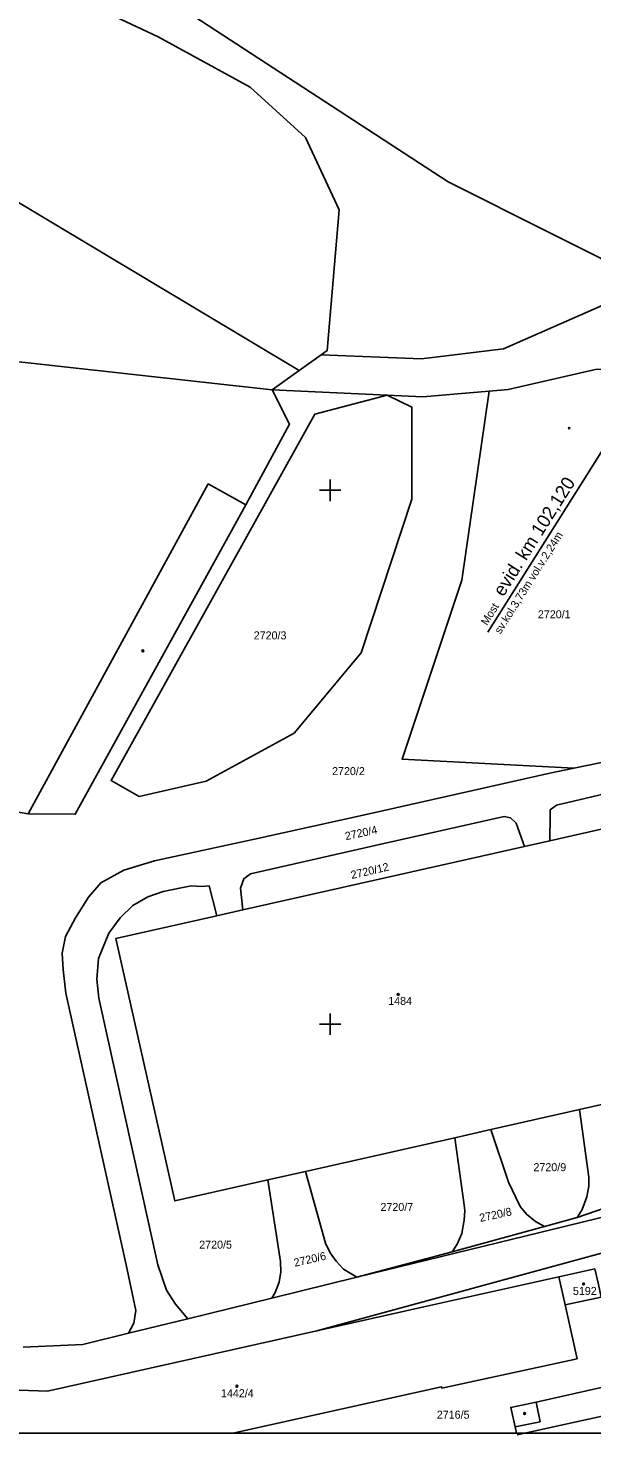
# Model space of a CAD drawing. Extents: x -800194 to -799078, y -1007177 to -1006597.
# Drawn here: x -799956.6 to -799850.9, y -1007177 to -1006913.4 of the extents above; entities that cross this region are included whole.
import ezdxf

# ---------------------------------------------------------------- set-up
doc = ezdxf.new("R2010")
doc.units = 0
for name, color, linetype in [('Legenda 1', 7, 'Continuous'), ('Ramove udaje', 7, 'Continuous'), ('Vrstva 18', 7, 'Continuous'), ('Vrstva 49', 7, 'Continuous'), ('Vrstva 53', 7, 'Continuous'), ('Vrstva 55', 7, 'Continuous'), ('Vrstva 56', 7, 'Continuous'), ('Vrstva 57', 7, 'Continuous'), ('Vrstva 59', 7, 'Continuous')]:
    doc.layers.add(name, color=color, linetype=linetype)

msp = doc.modelspace()

# ---------------------------------------------------------------- linework, layer by layer
at = {"layer": 'Legenda 1'}
msp.add_lwpolyline([(-800193.4, -1007176.65), (-799312.4, -1007176.65), (-799312.4, -1006766.65), (-800193.4, -1006766.65)], close=True, dxfattribs=at)
at = {"layer": 'Ramove udaje'}
for p, q in [((-799900, -1006998), (-799900, -1007002)), ((-799902, -1007000), (-799900, -1007000)), ((-799900, -1007000), (-799898, -1007000)), ((-799900, -1007098), (-799900, -1007102)), ((-799902, -1007100), (-799900, -1007100)), ((-799900, -1007100), (-799898, -1007100))]:
    msp.add_line(p, q, dxfattribs=at)
at = {"layer": 'Vrstva 18'}
msp.add_line((-799827.91, -1006959.09), (-799870.44, -1007026.56), dxfattribs=at)
at = {"layer": 'Vrstva 49'}
for p, q in [((-799855.35, -1006988.18), (-799855, -1006988.53)), ((-799855.35, -1006988.53), (-799855, -1006988.18))]:
    msp.add_line(p, q, dxfattribs=at)
at = {"layer": 'Vrstva 53'}
msp.add_lwpolyline([(-799673.33, -1007118.14), (-799714.71, -1007110.97), (-799718.21, -1007083.69), (-799729.93, -1007087.54), (-799766.47, -1007095.84), (-799767.73, -1007094.8), (-799769.22, -1007093.56), (-799785.06, -1007080.42), (-799809.11, -1007056.81), (-799818.59, -1007034.4), (-799822.79, -1007029.13), (-799826.14, -1007024.13), (-799830.75, -1006966.73), (-799839.73, -1006961.33), (-799877.87, -1006942.17), (-799936.47, -1006903.99), (-799954.76, -1006895.45), (-799964.79, -1006890.84)], dxfattribs=at)
at = {"layer": 'Vrstva 55'}
for p, q in [((-799905.8, -1006977.56), (-800048.34, -1006892.35)), ((-799905.8, -1006977.56), (-799901.69, -1006974.63)), ((-799901.69, -1006974.63), (-799882.85, -1006975.35)), ((-799910.85, -1006981.15), (-799905.8, -1006977.56)), ((-799870.16, -1006981.42), (-799878.32, -1006982.12)), ((-799866.6, -1006981.12), (-799870.16, -1006981.42)), ((-799858.8, -1007053.02), (-799854.29, -1007052.07)), ((-799854.29, -1007052.07), (-799846.07, -1007050.35)), ((-799863.56, -1007066.73), (-799916.37, -1007078.61)), ((-799858.84, -1007065.67), (-799863.56, -1007066.73)), ((-799916.37, -1007078.61), (-799921.23, -1007079.7)), ((-799853.26, -1007116.03), (-799846.34, -1007114.47)), ((-799869.87, -1007119.78), (-799853.26, -1007116.03)), ((-799876.63, -1007121.3), (-799869.87, -1007119.78)), ((-799904.64, -1007127.61), (-799876.63, -1007121.3)), ((-799911.69, -1007129.2), (-799904.64, -1007127.61)), ((-799853.69, -1007136.27), (-799838.05, -1007130.83)), ((-799859.81, -1007137.94), (-799853.69, -1007136.27)), ((-799877.13, -1007142.66), (-799859.81, -1007137.94)), ((-799902.49, -1007157.51), (-799844.11, -1007141.59)), ((-799895.02, -1007147.45), (-799877.13, -1007142.66)), ((-799850.35, -1007145.84), (-799857.1, -1007147.35)), ((-799895.02, -1007147.45), (-799910.9, -1007151.34)), ((-799855.94, -1007152.6), (-799857.1, -1007147.35)), ((-799910.9, -1007151.34), (-799926.68, -1007155.21)), ((-799926.68, -1007155.21), (-799937.79, -1007157.93))]:
    msp.add_line(p, q, dxfattribs=at)
for points in [[(-799901.69, -1006974.63), (-799900.54, -1006973.82), (-799898.31, -1006947.43), (-799904.63, -1006933.89), (-799915, -1006924.46), (-799932.22, -1006915.03), (-799953.17, -1006905.18), (-799968.93, -1006898.86), (-799993.08, -1006892.39), (-800012.71, -1006890.11), (-800033.89, -1006890), (-800048.34, -1006892.35)], [(-799839.73, -1006961.33), (-799877.87, -1006942.17), (-799936.47, -1006903.99), (-799954.76, -1006895.45), (-799964.79, -1006890.84)], [(-800126.38, -1006954.46), (-800114.82, -1006956.57), (-800087.75, -1006960.99), (-799990.59, -1006972.38), (-799910.85, -1006981.15)], [(-799882.85, -1006975.35), (-799867.48, -1006973.49), (-799839.73, -1006961.33)], [(-799831.14, -1007046.62), (-799837.54, -1006984.31), (-799843.2, -1006977.69), (-799849.98, -1006977.29), (-799866.6, -1006981.12)], [(-799910.85, -1006981.15), (-799907.6, -1006987.58), (-799915.79, -1007002.7), (-799947.77, -1007060.68), (-799956.59, -1007060.62), (-799959.22, -1007060.2), (-799959.32, -1007060.77), (-799959.99, -1007068.95), (-799959.15, -1007100.86), (-799958.55, -1007123.98)], [(-799889.28, -1006982.17), (-799884.71, -1006984.4), (-799884.66, -1007001.67), (-799894.18, -1007030.47), (-799906.77, -1007045.52), (-799923.26, -1007054.52), (-799935.81, -1007057.35), (-799941.05, -1007054.37), (-799902.88, -1006985.7), (-799889.28, -1006982.17)], [(-799882.61, -1006982.49), (-799889.28, -1006982.17), (-799910.85, -1006981.15)], [(-799870.16, -1006981.42), (-799875.33, -1007016.85), (-799886.5, -1007050.4), (-799854.29, -1007052.07)], [(-799878.32, -1006982.12), (-799881.11, -1006982.36), (-799882.61, -1006982.49)], [(-799937.79, -1007157.93), (-799936.82, -1007156.03), (-799936.45, -1007153.7), (-799938.22, -1007145.09), (-799949.52, -1007094.24), (-799950.07, -1007089.8), (-799950.22, -1007086.71), (-799949.61, -1007083.61), (-799947.74, -1007080.12), (-799945.31, -1007076.24), (-799942.96, -1007073.53), (-799938.68, -1007071.19), (-799932.9, -1007069.42), (-799914.16, -1007065.36), (-799892.71, -1007060.59), (-799858.8, -1007053.02)], [(-799858.84, -1007065.67), (-799858.76, -1007060.77), (-799858.72, -1007059.86), (-799857.59, -1007058.97), (-799845.38, -1007056.13), (-799841.77, -1007056.79), (-799839.5, -1007058.21), (-799837.43, -1007060.68), (-799836.99, -1007067.77), (-799836.14, -1007072.71), (-799834.61, -1007079.6), (-799832.83, -1007084.94), (-799830.58, -1007092.52), (-799828.9, -1007096.44), (-799827.32, -1007101.2), (-799825.89, -1007106.02), (-799824.52, -1007111.92), (-799824.25, -1007121.19), (-799824.17, -1007122.98), (-799825.87, -1007124.09), (-799830.82, -1007128.75)], [(-799916.37, -1007078.61), (-799916.82, -1007074.54), (-799916.17, -1007072.79), (-799914.91, -1007071.85), (-799890.76, -1007066.36), (-799867.37, -1007061.12), (-799866.17, -1007061.36), (-799865.15, -1007062.35), (-799863.56, -1007066.73)], [(-799846.34, -1007114.47), (-799834.79, -1007111.87), (-799845.89, -1007062.76), (-799858.84, -1007065.67)], [(-799926.68, -1007155.21), (-799928.97, -1007152.5), (-799930.66, -1007149.85), (-799932.29, -1007145.14), (-799943.36, -1007095.14), (-799943.76, -1007091.6), (-799943.45, -1007087.73), (-799941.48, -1007082.96), (-799939.34, -1007080.12), (-799936.97, -1007077.8), (-799934.15, -1007076.19), (-799931.27, -1007075.17), (-799926.04, -1007074.1), (-799924.08, -1007074.23), (-799922.66, -1007074.11), (-799921.23, -1007079.7)], [(-799921.23, -1007079.7), (-799940.15, -1007083.96), (-799929.14, -1007133.13), (-799911.69, -1007129.2)], [(-799853.69, -1007136.27), (-799852.72, -1007134.73), (-799851.85, -1007132.41), (-799851.49, -1007130.4), (-799851.51, -1007128.69), (-799851.8, -1007126.44), (-799853.26, -1007116.03)], [(-799859.81, -1007137.94), (-799861.51, -1007136.99), (-799863.16, -1007135.61), (-799864.37, -1007134.2), (-799866.53, -1007129.66), (-799869.87, -1007119.78)], [(-799877.13, -1007142.66), (-799876.18, -1007141.27), (-799875.3, -1007139.22), (-799874.85, -1007136.77), (-799874.75, -1007134.96), (-799875, -1007132.95), (-799875.06, -1007132.59), (-799876.63, -1007121.3)], [(-799814.24, -1007125.43), (-799822.76, -1007128.21), (-799844.82, -1007135.16), (-799895.02, -1007147.45)], [(-799895.02, -1007147.45), (-799897.49, -1007145.93), (-799898.84, -1007144.45), (-799900.01, -1007142.86), (-799900.88, -1007141.07), (-799904.64, -1007127.61)], [(-799910.9, -1007151.34), (-799910.28, -1007150.28), (-799909.58, -1007148.38), (-799909.26, -1007146.44), (-799909.31, -1007144.47), (-799911.69, -1007129.2)], [(-799855.94, -1007152.6), (-799849.17, -1007151.19), (-799849.68, -1007148.8), (-799850.35, -1007145.84)], [(-799857.1, -1007147.35), (-799882.44, -1007153.02), (-799902.49, -1007157.51)], [(-799918.24, -1007176.65), (-799879.14, -1007167.97), (-799879.08, -1007168.21), (-799853.7, -1007162.72), (-799855.94, -1007152.6)], [(-799902.49, -1007157.51), (-799953, -1007168.82), (-799958.28, -1007168.59), (-799967.15, -1007168.25), (-799970.47, -1007168.12)], [(-799957.55, -1007160.54), (-799946.38, -1007160.03), (-799937.79, -1007157.93)], [(-799839.36, -1007176.65), (-799840.49, -1007171.57), (-799842.09, -1007171.9), (-799842.85, -1007168.35), (-799846.6, -1007169.23), (-799847.19, -1007169.37), (-799847.51, -1007167.75), (-799861.36, -1007170.85), (-799866.14, -1007171.83), (-799865.33, -1007175.48), (-799865.03, -1007176.65)]]:
    msp.add_lwpolyline(points, dxfattribs=at)
at = {"layer": 'Vrstva 56'}
for p, q in [((-799922.84, -1006998.8), (-799956.59, -1007060.62)), ((-799922.84, -1006998.8), (-799915.79, -1007002.7)), ((-799861.36, -1007170.85), (-799860.6, -1007174.51)), ((-799864.94, -1007176.98), (-799845.85, -1007172.76)), ((-799860.6, -1007174.51), (-799865.33, -1007175.48))]:
    msp.add_line(p, q, dxfattribs=at)
at = {"layer": 'Vrstva 59'}
for centre in [(-799935.1, -1007030.07), (-799887.24, -1007094.44), (-799852.47, -1007148.71), (-799917.46, -1007167.86), (-799863.53, -1007172.98)]:
    msp.add_circle(centre, 0.175, dxfattribs=at)

# ---------------------------------------------------------------- texts
at = {"layer": 'Vrstva 18'}
for s, height, p in [('evid. km 102,120', 2.5, (-799867.51, -1007020.07)), ('sv.kol.3,73m vol.v.2,24m', 1.5, (-799868.05, -1007027.02)), ('Most', 1.5, (-799870.59, -1007025.42))]:
    msp.add_text(s, height=height, rotation=57.7746, dxfattribs=at).set_placement(p)
at = {"layer": 'Vrstva 57'}
for s, p in [('2720/1', (-799861.05, -1007023.98)), ('2720/3', (-799914.32, -1007027.93)), ('2720/2', (-799899.63, -1007053.36)), ('1484', (-799889.11, -1007096.42)), ('2720/9', (-799861.88, -1007127.57)), ('2720/7', (-799890.56, -1007135.03)), ('2720/5', (-799924.54, -1007142.09)), ('5192', (-799854.48, -1007150.76)), ('1442/4', (-799920.46, -1007169.93)), ('2716/5', (-799880, -1007173.95))]:
    msp.add_text(s, height=1.5, dxfattribs=at).set_placement(p)
for s, rotation, p in [('2720/4', 12, (-799897.04, -1007065.56)), ('2720/12', 13, (-799895.93, -1007072.84)), ('2720/8', 12, (-799871.84, -1007137.09)), ('2720/6', 13, (-799906.61, -1007145.49))]:
    msp.add_text(s, height=1.5, rotation=rotation, dxfattribs=at).set_placement(p)

doc.saveas('drawing.dxf')
